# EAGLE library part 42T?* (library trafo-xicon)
Xicon Micro-Mini EI-12 Audio Transformers 42TL/42TC/42TM Series Source: http://www.mouser.com//catalog/specsheets/164201.pdf http://www.mouser.com/catalog/specsheets/114225.pdf http://www.mouser.com/catalog/specsheets/164267.pdf
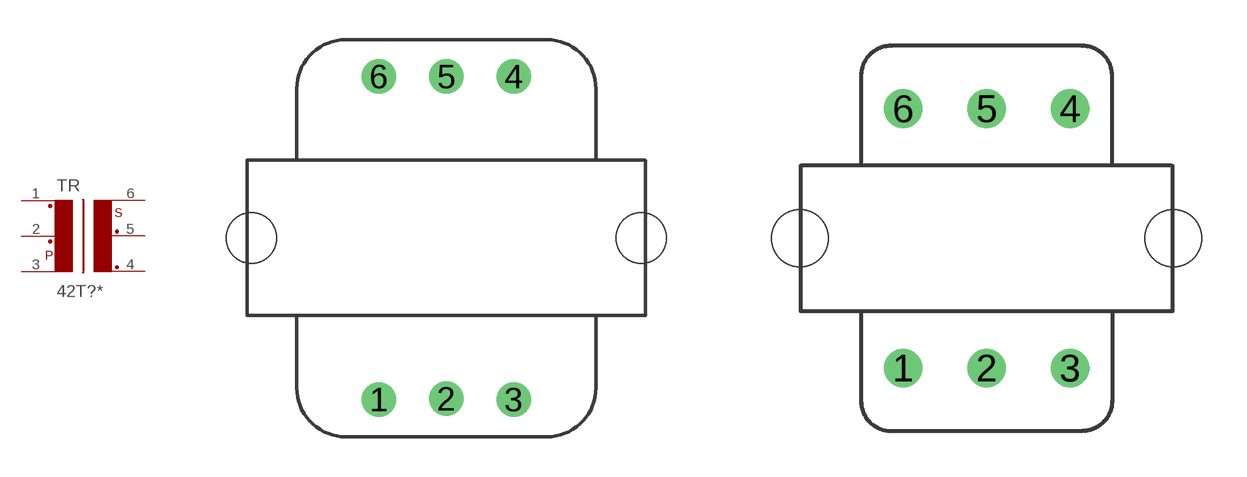
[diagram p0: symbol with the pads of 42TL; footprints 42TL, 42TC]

Designator prefix TR

## 42TL001 (OC_FARNELL: unknown; OC_NEWARK: unknown), 42TL002 (OC_FARNELL: unknown; OC_NEWARK: unknown), 42TL003 (OC_FARNELL: unknown; OC_NEWARK: unknown), 42TL004 (OC_FARNELL: unknown; OC_NEWARK: unknown), 42TL006 (OC_FARNELL: unknown; OC_NEWARK: unknown), 42TL008 (OC_FARNELL: unknown; OC_NEWARK: unknown), 42TL009 (OC_FARNELL: unknown; OC_NEWARK: unknown), 42TL011 (OC_FARNELL: unknown; OC_NEWARK: unknown), 42TL012 (OC_FARNELL: unknown; OC_NEWARK: unknown), 42TL013 (OC_FARNELL: unknown; OC_NEWARK: unknown), 42TL016 (OC_FARNELL: unknown; OC_NEWARK: unknown), 42TL017 (OC_FARNELL: unknown; OC_NEWARK: unknown), 42TL018 (OC_FARNELL: unknown; OC_NEWARK: unknown), 42TL019 (OC_FARNELL: unknown; OC_NEWARK: unknown), 42TL020 (OC_FARNELL: unknown; OC_NEWARK: unknown), 42TL021 (OC_FARNELL: unknown; OC_NEWARK: unknown), 42TL022 (OC_FARNELL: unknown; OC_NEWARK: unknown), 42TL023 (OC_FARNELL: unknown; OC_NEWARK: unknown), 42TL024 (OC_FARNELL: unknown; OC_NEWARK: unknown), 42TL025 (OC_FARNELL: unknown; OC_NEWARK: unknown), 42TL026 (OC_FARNELL: unknown; OC_NEWARK: unknown), 42TL027 (OC_FARNELL: unknown; OC_NEWARK: unknown), 42TL030 (OC_FARNELL: unknown; OC_NEWARK: unknown), 42TL031 (OC_FARNELL: unknown; OC_NEWARK: unknown), 42TL218 (OC_FARNELL: unknown; OC_NEWARK: unknown)  [42TL]
1  1  pas
2  2  pas
3  3  pas
4  4  pas
5  5  pas
6  6  pas

## 42TC001 (OC_FARNELL: unknown; OC_NEWARK: unknown), 42TC013 (OC_FARNELL: unknown; OC_NEWARK: unknown), 42TC016 (OC_FARNELL: unknown; OC_NEWARK: unknown)  [42TC]
Pads as for 42TL

## 42TC019 (OC_FARNELL: unknown; OC_NEWARK: unknown), 42TC021 (OC_FARNELL: unknown; OC_NEWARK: unknown), 42TC030 (OC_FARNELL: unknown; OC_NEWARK: unknown)  [42TC]
1  4  pas
2  5  pas
3  6  pas
4  1  pas
5  2  pas
6  3  pas

## 42TM001 (OC_FARNELL: unknown; OC_NEWARK: unknown), 42TM002 (OC_FARNELL: unknown; OC_NEWARK: unknown), 42TM003 (OC_FARNELL: unknown; OC_NEWARK: unknown), 42TM004 (OC_FARNELL: unknown; OC_NEWARK: unknown), 42TM006 (OC_FARNELL: unknown; OC_NEWARK: unknown), 42TM008 (OC_FARNELL: unknown; OC_NEWARK: unknown), 42TM009 (OC_FARNELL: unknown; OC_NEWARK: unknown), 42TM010 (OC_FARNELL: unknown; OC_NEWARK: unknown), 42TM011 (OC_FARNELL: unknown; OC_NEWARK: unknown), 42TM012 (OC_FARNELL: unknown; OC_NEWARK: unknown), 42TM013 (OC_FARNELL: unknown; OC_NEWARK: unknown), 42TM016 (OC_FARNELL: unknown; OC_NEWARK: unknown), 42TM017 (OC_FARNELL: unknown; OC_NEWARK: unknown), 42TM018 (OC_FARNELL: unknown; OC_NEWARK: unknown), 42TM019 (OC_FARNELL: unknown; OC_NEWARK: unknown), 42TM020 (OC_FARNELL: unknown; OC_NEWARK: unknown), 42TM021 (OC_FARNELL: unknown; OC_NEWARK: unknown), 42TM022 (OC_FARNELL: unknown; OC_NEWARK: unknown), 42TM023 (OC_FARNELL: unknown; OC_NEWARK: unknown), 42TM024 (OC_FARNELL: unknown; OC_NEWARK: unknown), 42TM025 (OC_FARNELL: unknown; OC_NEWARK: unknown), 42TM026 (OC_FARNELL: unknown; OC_NEWARK: unknown), 42TM027 (OC_FARNELL: unknown; OC_NEWARK: unknown), 42TM030 (OC_FARNELL: unknown; OC_NEWARK: unknown), 42TM031 (OC_FARNELL: unknown; OC_NEWARK: unknown), 42TM114 (OC_FARNELL: unknown; OC_NEWARK: unknown), 42TM117 (OC_FARNELL: unknown; OC_NEWARK: unknown), 42TM118 (OC_FARNELL: unknown; OC_NEWARK: unknown)  [42TM]
Pads as for 42TL

## Footprint 42TL (pad centres in mm)
Xicon Ultra-Mini Audio Transformer 42TL Series Category: Audio & Signal Transformers Source: http://www.mouser.com//catalog/specsheets/164201.pdf
drill 0.7 pad 1.3 round: 1 -2.54,-6.096; 2 0,-6.068; 3 2.54,-6.096; 4 2.54,6.096; 5 0,6.096; 6 -2.54,6.096
hole 1.9 at -7.353,0
hole 1.9 at 7.353,0

## Footprint 42TC (pad centres in mm)
Xicon Ultra-Mini Audio Transformer 42TC Series Source: http://www.mouser.com/catalog/specsheets/114225.pdf
drill 0.7 pad 1.3 round: 1 -2.794,-4.343; 2 0,-4.343; 3 2.794,-4.343; 4 2.794,4.343; 5 0,4.343; 6 -2.794,4.343
hole 1.9 at -6.248,0
hole 1.9 at 6.248,0

## Footprint 42TM (pad centres in mm)
Xicon Ultra-Mini Audio Transformer 42TM Series Source: http://www.mouser.com/catalog/specsheets/164267.pdf
drill 0.7 pad 1.3 round: 1 -3.556,-6.35; 2 0,-6.35; 3 3.556,-6.35; 4 3.556,6.35; 5 0,6.35; 6 -3.556,6.35
hole 1.9 at -9.982,0
hole 1.9 at 9.982,0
